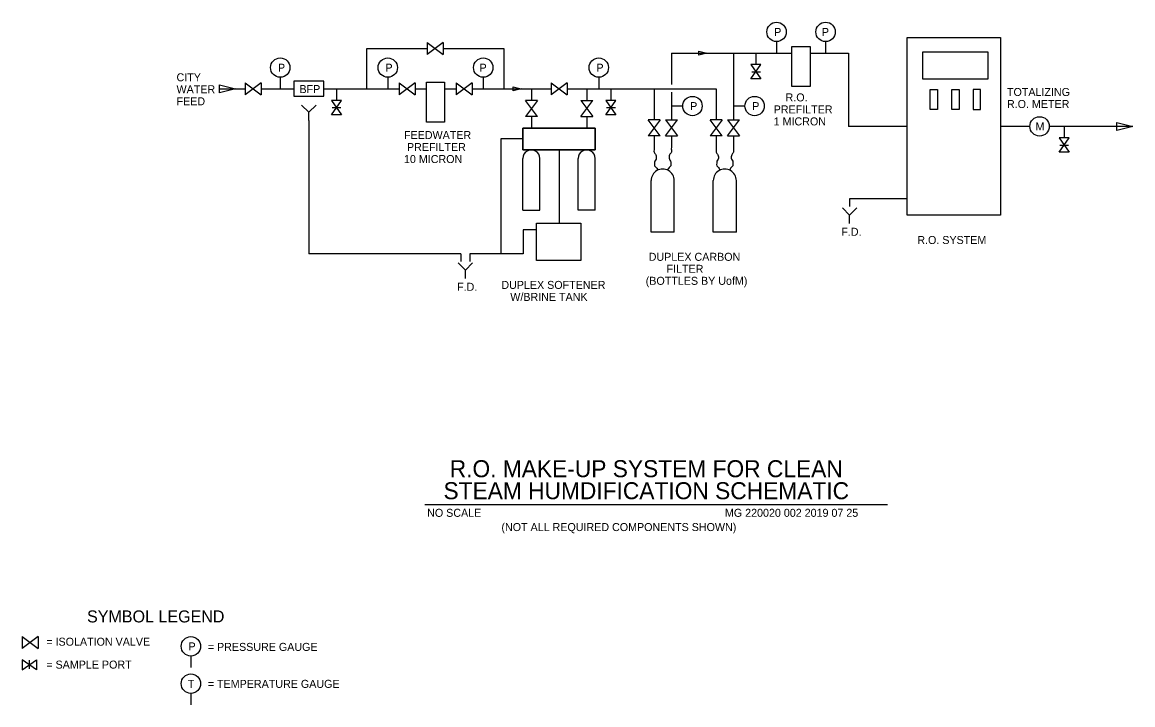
# Model space of a CAD drawing. Extents: x 9936.5 to 10029, y 10037.8 to 10094.7.
import ezdxf

# ---------------------------------------------------------------- set-up
doc = ezdxf.new("R2010")
doc.units = 0
for name, color, linetype in [('G-ANNO-CELL', 7, 'Continuous'), ('G-ANNO-TEXT', 7, 'Continuous'), ('M-STEM-CONP', 7, 'Continuous')]:
    doc.layers.add(name, color=color, linetype=linetype)

msp = doc.modelspace()

# ---------------------------------------------------------------- linework, layer by layer
at = {"layer": 'G-ANNO-CELL'}
msp.add_line((9970.075, 10054.502), (10008.6, 10054.502), dxfattribs=at)
at = {"layer": 'G-ANNO-TEXT'}
for p, q in [((9999.359, 10093.045), (9999.359, 10092.091)), ((10003.445, 10093.045), (10003.445, 10092.091)), ((9958.02, 10090.072), (9958.02, 10089.118)), ((9966.979, 10090.072), (9966.979, 10089.118)), ((9974.931, 10090.072), (9974.931, 10089.118)), ((9984.552, 10090.072), (9984.552, 10089.118)), ((9960.399, 10087.162), (9959.796, 10087.766)), ((9960.399, 10087.162), (9961.003, 10087.766)), ((9991.55, 10087.68), (9990.597, 10087.68)), ((9996.725, 10087.68), (9995.771, 10087.68)), ((9960.399, 10086.463), (9960.399, 10087.162)), ((9960.399, 10086.463), (9960.399, 10075.383)), ((9978.226, 10084.941), (9976.398, 10084.941)), ((9976.398, 10084.941), (9976.398, 10075.383)), ((9981.241, 10084.032), (9981.241, 10077.915)), ((9978.226, 10079.019), (9978.226, 10083.318)), ((9979.645, 10079.019), (9979.645, 10083.318)), ((9982.836, 10079.019), (9982.836, 10083.318)), ((9984.255, 10079.019), (9984.255, 10083.318)), ((9988.916, 10077.173), (9988.916, 10081.472)), ((9990.838, 10077.173), (9990.838, 10081.472)), ((9994.09, 10077.173), (9994.09, 10081.472)), ((9996.012, 10077.173), (9996.012, 10081.472)), ((10010.243, 10079.964), (10005.445, 10079.964)), ((10005.445, 10079.964), (10005.445, 10079.306)), ((9978.226, 10079.019), (9979.645, 10079.019)), ((9984.255, 10079.019), (9982.836, 10079.019)), ((10005.445, 10078.604), (10004.841, 10079.207)), ((10005.445, 10078.604), (10006.049, 10079.207)), ((10005.445, 10077.905), (10005.445, 10078.604)), ((9979.379, 10077.357), (9978.241, 10077.357)), ((9978.241, 10077.357), (9978.241, 10075.383)), ((9990.838, 10077.173), (9988.916, 10077.173)), ((9996.012, 10077.173), (9994.09, 10077.173)), ((9973.063, 10075.383), (9960.399, 10075.383)), ((9973.063, 10075.383), (9973.063, 10074.725)), ((9978.241, 10075.383), (9973.821, 10075.383)), ((9973.821, 10075.383), (9973.821, 10074.725)), ((9973.442, 10074.023), (9972.839, 10074.626)), ((9973.442, 10074.023), (9974.046, 10074.626)), ((9973.442, 10073.324), (9973.442, 10074.023)), ((9936.526, 10043.49), (9936.526, 10042.49)), ((9936.526, 10043.49), (9937.859, 10042.49)), ((9937.859, 10043.49), (9936.526, 10042.49)), ((9937.859, 10043.49), (9937.859, 10042.49)), ((9936.526, 10041.569), (9936.526, 10040.736)), ((9936.526, 10040.736), (9937.716, 10041.569)), ((9937.716, 10040.736), (9936.526, 10041.569)), ((9937.121, 10040.802), (9937.121, 10041.533)), ((9937.716, 10041.569), (9937.716, 10040.736)), ((9950.578, 10041.873), (9950.578, 10040.92)), ((9950.578, 10038.766), (9950.578, 10037.813))]:
    msp.add_line(p, q, dxfattribs=at)
for points in [[(10010.252, 10093.378), (10018.013, 10093.378), (10018.013, 10078.594), (10010.252, 10078.594)], [(10000.646, 10092.633), (10002.158, 10092.633), (10002.158, 10089.301), (10000.646, 10089.301)], [(10011.545, 10092.208), (10016.966, 10092.208), (10016.966, 10089.928), (10011.545, 10089.928)], [(9970.199, 10089.66), (9971.711, 10089.66), (9971.711, 10086.328), (9970.199, 10086.328)], [(10012.159, 10089.044), (10012.775, 10089.044), (10012.775, 10087.381), (10012.159, 10087.381)], [(10013.948, 10089.044), (10014.564, 10089.044), (10014.564, 10087.381), (10013.948, 10087.381)], [(10016.352, 10089.044), (10015.736, 10089.044), (10015.736, 10087.381), (10016.352, 10087.381)], [(9978.226, 10085.849), (9984.255, 10085.849), (9984.255, 10084.032), (9978.226, 10084.032)], [(9984.255, 10085.849), (9978.226, 10085.849), (9978.226, 10084.032), (9984.255, 10084.032)], [(9979.379, 10077.915), (9983.058, 10077.915), (9983.058, 10074.812), (9979.379, 10074.812)]]:
    msp.add_lwpolyline(points, close=True, dxfattribs=at)
for centre in [(9999.359, 10093.853), (10003.445, 10093.853), (9958.02, 10090.88), (9966.979, 10090.88), (9974.931, 10090.88), (9984.552, 10090.88), (9992.358, 10087.68), (9997.533, 10087.68), (10021.272, 10085.986), (9950.578, 10042.681), (9950.578, 10039.574)]:
    msp.add_circle(centre, 0.808, dxfattribs=at)
for centre, radius, start, end in [((9978.936, 10083.318), 0.709, 359.99989, 180), ((9983.545, 10083.318), 0.709, 0, 180.00011), ((9989.877, 10081.472), 0.961, 0, 180.00009), ((9995.051, 10081.472), 0.961, 0, 180.00009)]:
    msp.add_arc(centre, radius, start, end, dxfattribs=at)
at = {"layer": 'M-STEM-CONP'}
for p, q in [((9970.264, 10092.962), (9970.264, 10091.962)), ((9970.264, 10092.962), (9971.598, 10091.962)), ((9971.598, 10092.962), (9970.264, 10091.962)), ((9971.598, 10092.962), (9971.598, 10091.962)), ((9965.232, 10089.118), (9965.232, 10092.462)), ((9965.232, 10092.462), (9970.264, 10092.462)), ((9971.598, 10092.462), (9976.631, 10092.462)), ((9976.631, 10092.462), (9976.631, 10089.118)), ((9990.597, 10092.091), (9990.597, 10089.46)), ((9990.597, 10092.091), (10000.646, 10092.091)), ((9995.771, 10092.091), (9995.771, 10086.538)), ((9997.643, 10092.091), (9997.643, 10091.127)), ((10002.158, 10092.091), (10005.35, 10092.091)), ((10005.35, 10092.091), (10005.35, 10085.986)), ((9998.059, 10091.127), (9997.226, 10091.127)), ((9997.226, 10091.127), (9998.059, 10089.937)), ((9997.226, 10089.937), (9998.059, 10091.127)), ((9997.292, 10090.532), (9998.023, 10090.532)), ((9952.958, 10089.118), (9955.09, 10089.118)), ((9955.09, 10089.618), (9955.09, 10088.618)), ((9955.09, 10089.618), (9956.423, 10088.618)), ((9956.423, 10089.618), (9955.09, 10088.618)), ((9956.423, 10089.618), (9956.423, 10088.618)), ((9956.423, 10089.118), (9959.156, 10089.118)), ((9961.656, 10089.118), (9967.913, 10089.118)), ((9962.697, 10089.107), (9962.697, 10088.143)), ((9967.913, 10089.618), (9967.913, 10088.618)), ((9967.913, 10089.618), (9969.246, 10088.618)), ((9969.246, 10089.618), (9967.913, 10088.618)), ((9969.246, 10089.618), (9969.246, 10088.618)), ((9969.246, 10089.118), (9970.199, 10089.118)), ((9971.711, 10089.118), (9972.664, 10089.118)), ((9972.664, 10089.618), (9972.664, 10088.618)), ((9973.997, 10089.618), (9972.664, 10088.618)), ((9972.664, 10089.618), (9973.997, 10088.618)), ((9973.997, 10089.618), (9973.997, 10088.618)), ((9973.997, 10089.118), (9980.574, 10089.118)), ((9978.936, 10089.107), (9978.936, 10088.143)), ((9980.574, 10089.618), (9980.574, 10088.618)), ((9980.574, 10089.618), (9981.907, 10088.618)), ((9981.907, 10089.618), (9980.574, 10088.618)), ((9981.907, 10089.618), (9981.907, 10088.618)), ((9981.907, 10089.118), (9994.331, 10089.118)), ((9983.545, 10089.107), (9983.545, 10088.143)), ((9985.559, 10089.107), (9985.559, 10088.143)), ((9989.157, 10089.118), (9989.157, 10086.538)), ((9994.331, 10089.118), (9994.331, 10086.538)), ((9998.059, 10089.937), (9997.226, 10089.937)), ((9990.597, 10088.822), (9990.597, 10086.538)), ((9963.114, 10088.143), (9962.28, 10088.143)), ((9962.28, 10088.143), (9963.114, 10086.953)), ((9962.28, 10086.953), (9963.114, 10088.143)), ((9962.332, 10087.548), (9963.062, 10087.548)), ((9979.436, 10088.143), (9978.436, 10088.143)), ((9979.436, 10088.143), (9978.436, 10086.81)), ((9979.436, 10086.81), (9978.436, 10088.143)), ((9983.045, 10088.143), (9984.045, 10088.143)), ((9983.045, 10088.143), (9984.045, 10086.81)), ((9983.045, 10086.81), (9984.045, 10088.143)), ((9985.976, 10088.143), (9985.143, 10088.143)), ((9985.143, 10088.143), (9985.976, 10086.953)), ((9985.143, 10086.953), (9985.976, 10088.143)), ((9985.209, 10087.548), (9985.939, 10087.548)), ((9963.114, 10086.953), (9962.28, 10086.953)), ((9979.436, 10086.81), (9978.436, 10086.81)), ((9978.936, 10086.81), (9978.936, 10085.849)), ((9983.045, 10086.81), (9984.045, 10086.81)), ((9983.545, 10086.81), (9983.545, 10085.849)), ((9985.976, 10086.953), (9985.143, 10086.953)), ((9989.657, 10086.538), (9988.657, 10086.538)), ((9989.657, 10086.538), (9988.657, 10085.205)), ((9989.657, 10085.205), (9988.657, 10086.538)), ((9990.097, 10086.538), (9991.097, 10086.538)), ((9990.097, 10086.538), (9991.097, 10085.205)), ((9990.097, 10085.205), (9991.097, 10086.538)), ((9994.831, 10086.538), (9993.831, 10086.538)), ((9994.831, 10086.538), (9993.831, 10085.205)), ((9994.831, 10085.205), (9993.831, 10086.538)), ((9995.271, 10086.538), (9996.271, 10086.538)), ((9995.271, 10086.538), (9996.271, 10085.205)), ((9995.271, 10085.205), (9996.271, 10086.538)), ((10010.252, 10085.986), (10005.35, 10085.986)), ((10020.464, 10085.986), (10018.013, 10085.986)), ((10029.035, 10085.986), (10022.08, 10085.986)), ((10023.306, 10085.986), (10023.306, 10085.022)), ((9989.657, 10085.205), (9988.657, 10085.205)), ((9989.157, 10085.205), (9989.157, 10084.244)), ((9990.097, 10085.205), (9991.097, 10085.205)), ((9990.597, 10085.205), (9990.597, 10084.244)), ((9994.831, 10085.205), (9993.831, 10085.205)), ((9994.331, 10085.205), (9994.331, 10084.244)), ((9995.271, 10085.205), (9996.271, 10085.205)), ((9995.771, 10085.205), (9995.771, 10084.244)), ((10023.723, 10085.022), (10022.889, 10085.022)), ((10022.889, 10085.022), (10023.723, 10083.831)), ((10022.889, 10083.831), (10023.723, 10085.022)), ((10023.723, 10083.831), (10022.889, 10083.831)), ((10022.956, 10084.427), (10023.686, 10084.427))]:
    msp.add_line(p, q, dxfattribs=at)
for points in [[(9992.878, 10092.258), (9993.544, 10092.091), (9992.878, 10091.925)], [(9952.963, 10089.452), (9954.296, 10089.118), (9952.963, 10088.785)], [(9961.656, 10089.743), (9959.156, 10089.743), (9959.156, 10088.493), (9961.656, 10088.493)], [(9977.43, 10089.285), (9978.096, 10089.118), (9977.43, 10088.952)], [(10027.702, 10086.319), (10029.035, 10085.986), (10027.702, 10085.653)]]:
    msp.add_lwpolyline(points, close=True, dxfattribs=at)
for points in [[(9989.155, 10084.226), (9989.155, 10084.026), (9989.155, 10083.826), (9989.304, 10083.627), (9989.338, 10083.444), (9989.321, 10083.26), (9989.221, 10083.094), (9989.205, 10082.911), (9989.205, 10082.711), (9989.338, 10082.562), (9989.438, 10082.412), (9989.454, 10082.345)], [(9990.599, 10084.226), (9990.599, 10084.026), (9990.599, 10083.826), (9990.449, 10083.627), (9990.416, 10083.444), (9990.432, 10083.26), (9990.532, 10083.094), (9990.549, 10082.911), (9990.549, 10082.711), (9990.416, 10082.562), (9990.316, 10082.412), (9990.299, 10082.345)], [(9994.329, 10084.226), (9994.329, 10084.026), (9994.329, 10083.826), (9994.479, 10083.627), (9994.512, 10083.444), (9994.496, 10083.26), (9994.396, 10083.094), (9994.379, 10082.911), (9994.379, 10082.711), (9994.512, 10082.562), (9994.612, 10082.412), (9994.629, 10082.345)], [(9995.773, 10084.226), (9995.773, 10084.026), (9995.773, 10083.826), (9995.624, 10083.627), (9995.59, 10083.444), (9995.607, 10083.26), (9995.707, 10083.094), (9995.723, 10082.911), (9995.723, 10082.711), (9995.59, 10082.562), (9995.49, 10082.412), (9995.474, 10082.345)]]:
    msp.add_spline(points, degree=3, dxfattribs=at)

# ---------------------------------------------------------------- texts
at = {"layer": 'G-ANNO-CELL'}
for s, height, p in [('R.O. MAKE-UP SYSTEM FOR CLEAN', 1.41667, (9972.138, 10056.768)), ('STEAM HUMDIFICATION SCHEMATIC', 1.41667, (9971.616, 10054.934)), ('NO SCALE', 0.6667, (9970.256, 10053.467))]:
    msp.add_text(s, height=height, dxfattribs=at).set_placement(p)
at = {"layer": 'G-ANNO-TEXT'}
for s, height, p in [('P', 0.667, (9999.163, 10093.512)), ('P', 0.667, (10003.135, 10093.512)), ('P', 0.667, (9957.83, 10090.538)), ('P', 0.667, (9966.783, 10090.538)), ('P', 0.667, (9984.357, 10090.538)), ('CITY', 0.6667, (9949.38, 10089.741)), ('WATER', 0.6667, (9949.38, 10088.741)), ('TOTALIZING', 0.6667, (10018.555, 10088.516)), ('FEED', 0.6667, (9949.38, 10087.741)), ('    R.O.', 0.6667, (9999.122, 10088.066)), ('R.O. METER', 0.6667, (10018.555, 10087.516)), ('P', 0.667, (9992.163, 10087.338)), ('P', 0.667, (9997.337, 10087.338)), ('PREFILTER', 0.6667, (9999.122, 10087.066)), ('1 MICRON', 0.6667, (9999.122, 10086.066)), ('FEEDWATER', 0.6667, (9968.327, 10084.931)), (' PREFILTER', 0.6667, (9968.327, 10083.931)), ('10 MICRON', 0.6667, (9968.327, 10082.931)), ('F.D.', 0.6667, (10004.754, 10076.873)), ('R.O. SYSTEM', 0.66667, (10011.088, 10076.19)), (' DUPLEX CARBON', 0.66667, (9988.463, 10074.789)), ('       FILTER', 0.66667, (9988.463, 10073.789)), ('(BOTTLES BY UofM)', 0.66667, (9988.463, 10072.789)), ('F.D.', 0.6667, (9972.751, 10072.292)), ('DUPLEX SOFTENER', 0.66667, (9976.437, 10072.449)), ('   W/BRINE TANK', 0.66667, (9976.437, 10071.449)), ('MG 220020 002 2019 07 25', 0.66667, (9995.062, 10053.467)), ('(NOT ALL REQUIRED COMPONENTS SHOWN)', 0.66667, (9976.445, 10052.281)), ('SYMBOL LEGEND', 1, (9941.927, 10044.672)), ('= ISOLATION VALVE', 0.66667, (9938.534, 10042.732)), ('P', 0.667, (9950.382, 10042.34)), ('= PRESSURE GAUGE', 0.66667, (9951.987, 10042.3)), ('= SAMPLE PORT', 0.66667, (9938.534, 10040.826)), ('T', 0.667, (9950.317, 10039.222)), ('= TEMPERATURE GAUGE', 0.66667, (9951.987, 10039.222))]:
    msp.add_text(s, height=height, dxfattribs=at).set_placement(p)
for s, p in [('P', (9974.621, 10090.538)), ('M', (10020.932, 10085.644))]:
    msp.add_text(s, height=0.667, rotation=360, dxfattribs=at).set_placement(p)
at = {"layer": 'M-STEM-CONP'}
msp.add_text('BFP', height=0.6667, dxfattribs=at).set_placement((9959.622, 10088.761))

doc.saveas('drawing.dxf')
